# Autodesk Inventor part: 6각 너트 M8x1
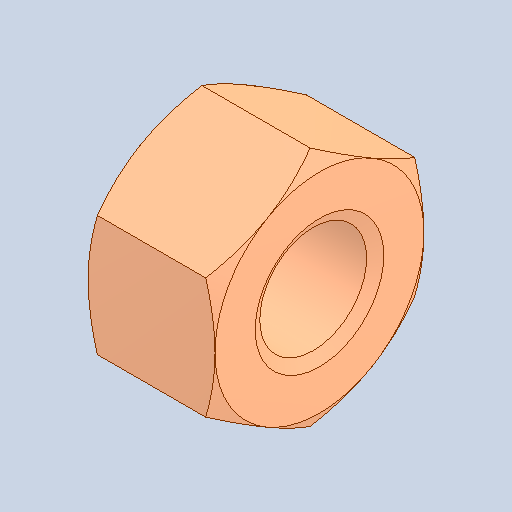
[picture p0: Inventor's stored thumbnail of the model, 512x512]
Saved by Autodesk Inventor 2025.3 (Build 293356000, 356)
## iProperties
Created: 2025-10
Part Number: 6각 너트 M8x1
Material: 강철, 연강
Description: 6각 너트 및 6각 가는 너트
Document SubType Name: Modeling
Designer: USER
Density: 7.85 g/cm^3
Appearance: 기본값
Author: jhkim
Sending System: Autodesk Inventor 2026
Preprocessor: ST-DEVELOPER v20.1
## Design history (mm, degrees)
feature "Solid1"
node "솔리드1"
